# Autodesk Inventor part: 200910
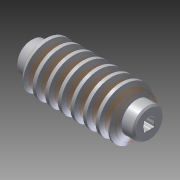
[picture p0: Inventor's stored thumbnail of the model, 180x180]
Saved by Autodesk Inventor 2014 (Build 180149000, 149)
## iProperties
Created: 2007-11
Part Number: 200910
Material: Acetal Resin, White
Document SubType Name: Modeling
Designer: JJ
Density: 1.42 g/cm^3
Mass: 5.8341 g
Surface Area: 32.5628 cm^2
Volume: 4.10852 cm^3
Description: WORM GEAR
Appearance: Smooth - White
CustomPartVersion: 1
Component Category: Lower Component
Author: JJ
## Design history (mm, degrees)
body "Solid1"
extrude "Base Body" new body stored distance "d6" = 30 (= da_b); taper "d7" = 0 deg
chamfer "Chamfer1" distance "d8" = 1.03584 (= fd_cham1); stored, may be unused: second distance "d9" = 2.84595 (= 0.5 x fd_cham2), angle "d47" = 45 deg
chamfer "Chamfer2" distance "d10" = 1.03584 (= fd_cham1); stored, may be unused: second distance "d11" = 2.84595 (= 0.5 x fd_cham2), angle "d48" = 45 deg
sketch "Tooth Sketch"
  geometry: L1 (0, 8.424)-(0, 4.331) reference; L2 (-19.803, 7.839)-(-18.739, 4.916); L3 (-17.837, 4.916)-(-16.773, 7.839); L4 (-16.345, 0)-(-12.103, 0) reference; L5 (-19.803, 7.839)-(-18.288, 7.839); L6 (-18.288, 7.839)-(-16.773, 7.839); L7 (-18.739, 4.916)-(-18.288, 4.916); L8 (-18.288, 4.916)-(-17.837, 4.916); L9 (-18.288, 6.468)-(-17.272, 6.468); L10 (-18.288, 7.839)-(-18.288, 4.916)
  constraints: 16 end point, 3 equal length, 3 parallel, 2 collinear, 2 point on line
  dimensions: "d24" = 110 deg angle of L7 L2 (computed from da_alfat); "d25" = 18.288 distance from line of L1 L5.end (= fd_dist); "d26" = 1.016 distance of L9.start L9.end (= 0.25 x da_px); "d27" = 4.91572 distance between parallel lines of L4 L7 (= 0.5 x da_df); "d28" = 6.46806 distance between parallel lines of L4 L9 (= 0.5 x da_d); "d29" = 7.83928 distance between parallel lines of L4 L5 (= 0.505 x da_da)
feature "Tooth" pitch "d30" = 4.064 (computed from da_px, da_z); turns "d32" = 10 (= fd_n); dims "d31" = 10, "d33" = 0, angle "d34" = 90 deg, angle "d35" = 90 deg, "d36" = 0, "d37" = 0, "d70" = 10, "da_rightdir" = 0 [user parameter]
pattern_circular "Tooth Pattern" dims angle "d46" = 360 deg, "da_rightdir" = 0 [user parameter]
feature "Left Tooth" pitch "d62" = 4.064 (computed from da_px, da_z); turns "d64" = 10 (= fd_n); dims "d63" = 10, "d65" = 0, angle "d66" = 90 deg, angle "d67" = 90 deg, "d68" = 0, "d69" = 0, "d76" = 10, "da_rightdir" = 0 [user parameter]
pattern_circular "Left Tooth Pattern" dims angle "d73" = 360 deg, "da_rightdir" = 0 [user parameter]
sketch "Sketch6"
  geometry: C1 r 4.866 at (0, 0); A1 r 4.916 centre (0, 0) between (4.656, -1.575) and (2.367, 4.308) reference; A2 r 4.916 centre (0, 0) between (2.367, 4.308) and (4.656, -1.575) reference
  constraints: 1 centre point, 1 coincident
  dimensions: "d83" = 0.05 radial gap between concentric circles of A2 C1
extrude "Extrusion2" join sketch "Sketch6" distance "d81" = 4; taper "d82" = 0 deg
chamfer "Chamfer3" distance "d84" = 0.5; stored, may be unused: second distance "d85" = 2, angle "d86" = 45 deg
revolve "Revolution1" stored, may be unused: angle "d89" = 90 deg
mirror "Mirror1"
sketch "Sketch8"
  geometry: L1 (-1.625, 1.625)-(1.625, 1.625); L2 (1.625, 1.625)-(1.625, -1.625); L3 (1.625, -1.625)-(-1.625, -1.625); L4 (-1.625, -1.625)-(-1.625, 1.625); C1 r 2.016 at (0, 0) reference; C2 r 4.366 at (0, 0) reference; C3 r 1.75 at (0, 0)
  constraints: 8 end point, 2 parallel, 1 centre point, 1 coincident, 1 horizontal, 1 perpendicular
  dimensions: "d90" = 3.25 distance of L1.start L1.end (= d91); "d91" = 3.25 distance of L1.end L2.end; "d92" = 1.625 distance from line of L1 C1.centre (= 0.5 x d91); "d93" = 1.625 distance from line of L4 C1.centre (= 0.5 x d90); "d96" = 3.5 diameter of C3
extrude "Extrusion3" cut sketch "Sketch8" stored distance "d94" = 10; taper "d95" = 0 deg
fillet "Fillet1" dims "d97" = 0.2
workaxis "Work Axis2"
node "Base Body Sketch" dims "d5" = 15.52334 (= da_da)
sketch "Sketch5"
  geometry: C1 r 7.762 at (0, 0) reference; C2 r 6.5 at (0, 0)
  constraints: 1 centre point, 1 coincident
  dimensions: "d59" = 13 diameter of C2
body "Srf1"
sketch "Sketch7"
  geometry: L1 (13.659, -4.916)-(12.757, -4.916) reference; L2 (11.721, -7.762)-(10.631, -7.762) reference; L3 (9.595, -4.916)-(8.693, -4.916) reference; L4 (7.657, -7.762)-(6.567, -7.762) reference; L5 (5.531, -4.916)-(4.629, -4.916) reference; L6 (3.593, -7.762)-(2.503, -7.762) reference; L7 (1.467, -4.916)-(0.565, -4.916) reference; L8 (-0.471, -7.762)-(-1.561, -7.762) reference; L9 (-2.597, -4.916)-(-3.499, -4.916) reference; L10 (15, 4.916)-(15, 4.866) reference; L11 (15, 4.866)-(18.5, 4.866) reference; L12 (18.5, 4.866)-(19, 4.366) reference; L13 (19, 4.366)-(19, -4.366) reference; L14 (19, -4.366)-(18.5, -4.866) reference; L15 (18.5, -4.866)-(15, -4.866) reference; L16 (15, -4.866)-(15, -4.916) reference; L17 (19, 0)-(27, 0); L18 (19, 0)-(18.75, 0); L19 (19, 0)-(19, 2.016); L20 (15, -4.916)-(14.329, -6.758) reference; L21 (-15, 4.916)-(-14.329, 6.758) reference; L22 (-4.535, -7.762)-(-5.625, -7.762) reference; L23 (-11.721, 7.762)-(-10.631, 7.762) reference; L24 (-13.659, 4.916)-(-12.757, 4.916) reference; L25 (-7.657, 7.762)-(-6.567, 7.762) reference; L26 (-9.595, 4.916)-(-8.693, 4.916) reference; L27 (14.789, 4.916)-(15, 4.916) reference; L28 (-6.661, -4.916)-(-7.563, -4.916) reference; L29 (-8.599, -7.762)-(-9.689, -7.762) reference; L30 (-10.725, -4.916)-(-11.627, -4.916) reference; L31 (-12.663, -7.762)-(-13.753, -7.762) reference; L32 (-14.789, -4.916)-(-15, -4.916) reference; L33 (-15, -4.916)-(-15, 4.916) reference; L34 (-5.531, 4.916)-(-4.629, 4.916) reference; L35 (-3.593, 7.762)-(-2.503, 7.762) reference; L36 (-1.467, 4.916)-(-0.565, 4.916) reference; L37 (0.471, 7.762)-(1.561, 7.762) reference; L38 (2.597, 4.916)-(3.499, 4.916) reference; L39 (4.535, 7.762)-(5.625, 7.762) reference; L40 (6.661, 4.916)-(7.563, 4.916) reference; L41 (8.599, 7.762)-(9.689, 7.762) reference; L42 (10.725, 4.916)-(11.627, 4.916) reference; L43 (12.663, 7.762)-(13.753, 7.762) reference; A1 r 8.25 centre (27, 0) between (19, 2.016) and (18.75, 0)
  constraints: 6 end point, 2 collinear, 2 point on circle, 1 centre point, 1 coincident, 1 midpoint, 1 perpendicular, 1 point on line, 30 other
  dimensions: "d87" = 8 distance of L17.start L17.end; "d88" = 16.5 diameter of A1
extrude_surface "ExtrusionSrf1" dims "d60" = 10, "d61" = 0
feature "Composite1"
node "Project Cut Edges1"
body "Srf2"
other parameters: "da_b" = 30 [user parameter; used in 3 equation terms], "da_df" = 9.83145 [user parameter; used in 2 equation terms], "da_da" = 15.52334 [user parameter; used in 3 equation terms], "fd_cham2" = 5.69189 (= da_da - da_df) [user parameter; used in 3 equation terms], "fd_cham1" = 1.03584 (= 0.181985 x fd_cham2) [user parameter; used in 2 equation terms], "da_d" = 12.93611 [user parameter; used in 1 equation term], "da_px" = 4.064 [user parameter; used in 5 equation terms], "fd_dist" = 18.288 (computed from da_b, da_px) [user parameter; used in 1 equation term], "fd_n" = 10 (computed from da_b, da_px) [user parameter; used in 2 equation terms], "da_alfat" = 20 deg [user parameter; used in 1 equation term], "d12" = 110 deg (derived), "d14" = 3.1425 (derived), "d50" = 0, "d54" = 0, "d56" = 0, "d77" = 0, "d80" = 0
